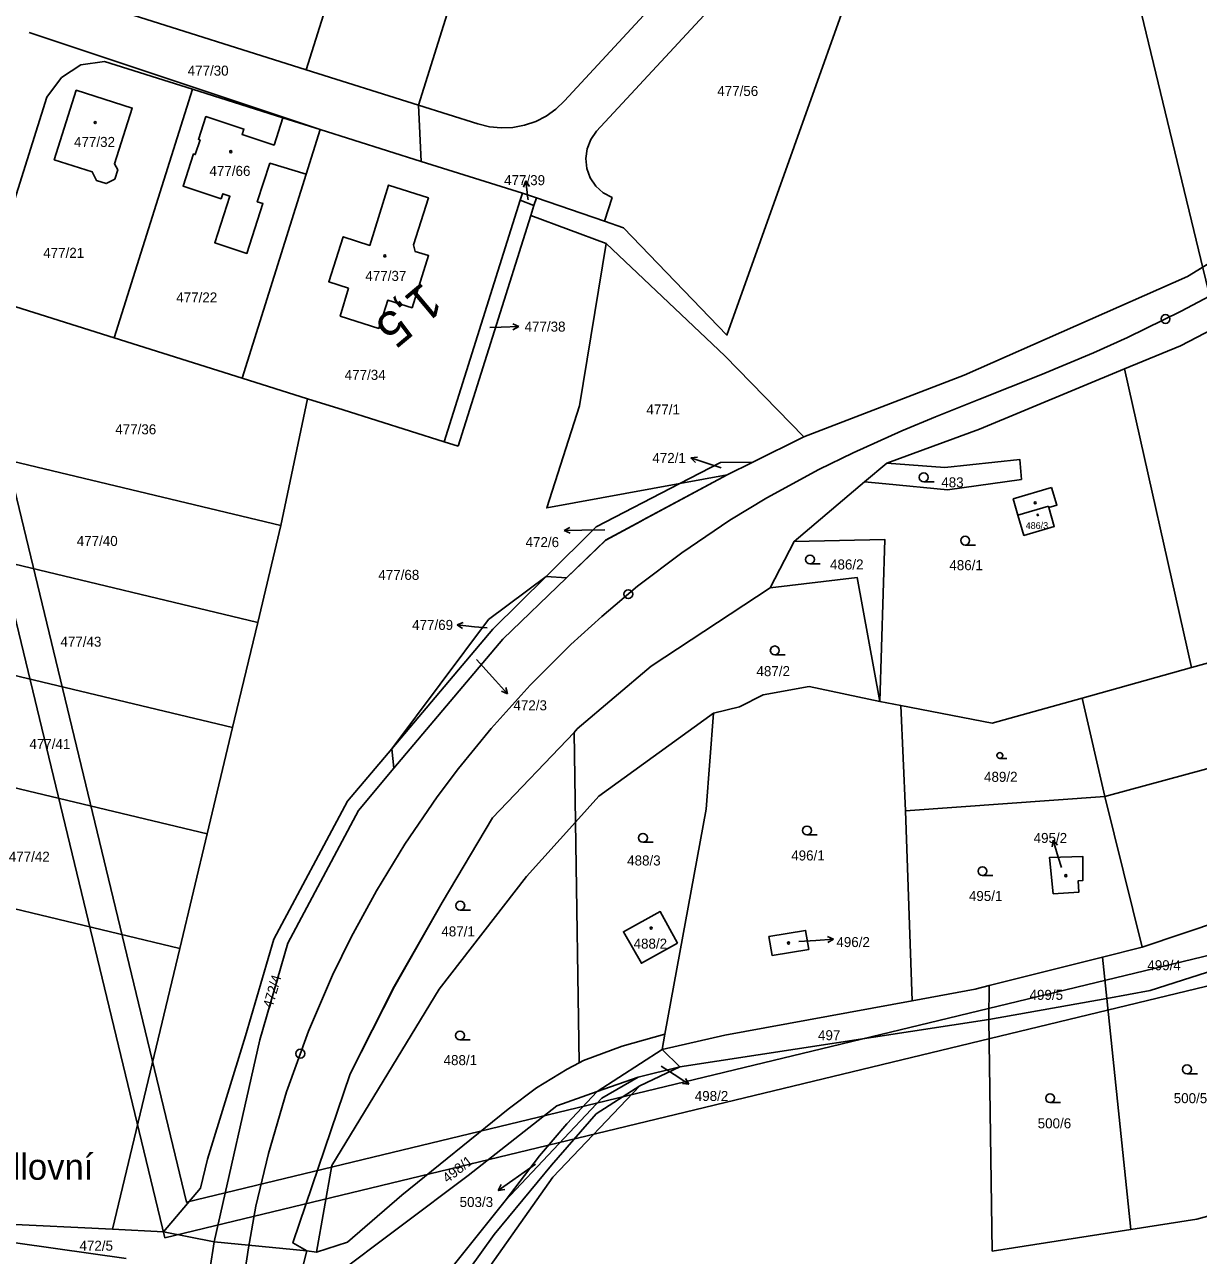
# Model space of a CAD drawing. Extents: x -738085 to -734306, y -1122197 to -1119753.
# Drawn here: x -735509 to -735309.7, y -1120522.6 to -1120313.6 of the extents above; entities that cross this region are included whole.
import ezdxf

# ---------------------------------------------------------------- set-up
doc = ezdxf.new("R2010")
doc.units = 0
for name, color, linetype in [('Hranice parcel', 7, 'Continuous'), ('Parcelní čísla', 7, 'Continuous'), ('Pop  PČ popisy', 7, 'Continuous'), ('SŽDC', 7, 'Continuous'), ('Vnitřní kresba', 7, 'Continuous'), ('Vrstva 1', 7, 'Continuous'), ('Vrstva 53', 7, 'Continuous'), ('Vrstva 7', 7, 'Continuous'), ('Značky budov', 7, 'Continuous'), ('Značky kultur', 7, 'Continuous')]:
    doc.layers.add(name, color=color, linetype=linetype)

msp = doc.modelspace()

# ---------------------------------------------------------------- linework, layer by layer
at = {"layer": 'Hranice parcel'}
for p, q in [((-735355.74, -1120271.01), (-735411.89, -1120331.72)), ((-735442.15, -1120327.29), (-735430.16, -1120289.05)), ((-735461.22, -1120321.27), (-735452.82, -1120294.56)), ((-735461.22, -1120321.27), (-735492.73, -1120311.32)), ((-735508.25, -1120314.94), (-735458.83, -1120331.44)), ((-735495.45, -1120319.9), (-735480.52, -1120324.6)), ((-735442.15, -1120327.29), (-735461.22, -1120321.27)), ((-735493.79, -1120366.81), (-735480.52, -1120324.6)), ((-735480.52, -1120324.6), (-735465.19, -1120329.44)), ((-735441.66, -1120336.85), (-735442.15, -1120327.29)), ((-735465.19, -1120329.44), (-735458.83, -1120331.44)), ((-735458.83, -1120331.44), (-735461.21, -1120339.02)), ((-735458.83, -1120331.44), (-735441.66, -1120336.85)), ((-735441.66, -1120336.85), (-735424.49, -1120342.25)), ((-735472.1, -1120373.63), (-735461.21, -1120339.02)), ((-735424.85, -1120343.41), (-735437.76, -1120384.43)), ((-735424.49, -1120342.25), (-735424.85, -1120343.41)), ((-735422.52, -1120344.32), (-735424.85, -1120343.41)), ((-735422.11, -1120343), (-735424.49, -1120342.25)), ((-735422.52, -1120344.32), (-735422.11, -1120343)), ((-735410.53, -1120347.01), (-735422.11, -1120343)), ((-735423.06, -1120346.03), (-735422.52, -1120344.32)), ((-735435.38, -1120385.18), (-735423.06, -1120346.03)), ((-735423.06, -1120346.03), (-735410.27, -1120350.77)), ((-735515.96, -1120359.84), (-735493.79, -1120366.81)), ((-735493.79, -1120366.81), (-735472.1, -1120373.63)), ((-735312.75, -1120368.12), (-735322.23, -1120372.05)), ((-735322.23, -1120372.05), (-735346.89, -1120382.27)), ((-735322.23, -1120372.05), (-735310.9, -1120422.76)), ((-735472.1, -1120373.63), (-735461, -1120377.12)), ((-735461, -1120377.12), (-735465.48, -1120398.66)), ((-735346.89, -1120382.27), (-735362.63, -1120388.07)), ((-735521.46, -1120385.26), (-735465.48, -1120398.66)), ((-735437.76, -1120384.43), (-735435.38, -1120385.18)), ((-735385.37, -1120387.89), (-735376.69, -1120383.59)), ((-735385.37, -1120387.89), (-735389.72, -1120390.04)), ((-735366.38, -1120391.25), (-735362.63, -1120388.07)), ((-735389.72, -1120390.04), (-735410.38, -1120401.13)), ((-735397.73, -1120391.51), (-735389.72, -1120390.04)), ((-735366.38, -1120391.25), (-735378.33, -1120401.35)), ((-735465.48, -1120398.66), (-735469.43, -1120415.11)), ((-735469.43, -1120415.11), (-735525.43, -1120401.67)), ((-735410.38, -1120401.13), (-735417.02, -1120407.52)), ((-735378.33, -1120401.35), (-735382.4, -1120409.22)), ((-735417.02, -1120407.52), (-735420.46, -1120407.28)), ((-735473.72, -1120432.96), (-735529.4, -1120419.6)), ((-735329.46, -1120427.95), (-735310.9, -1120422.76)), ((-735310.9, -1120422.76), (-735306.34, -1120421.48)), ((-735363.82, -1120428.54), (-735360.21, -1120429.23)), ((-735359.41, -1120447.11), (-735360.21, -1120429.23)), ((-735329.46, -1120427.95), (-735325.59, -1120444.65)), ((-735411.53, -1120444.57), (-735392.02, -1120430.49)), ((-735478, -1120451.01), (-735473.72, -1120432.96)), ((-735415.48, -1120448.98), (-735415.72, -1120433.76)), ((-735533.19, -1120437.76), (-735478, -1120451.01)), ((-735446.67, -1120436.55), (-735446.3, -1120439.84)), ((-735446.3, -1120439.84), (-735452.33, -1120447.02)), ((-735415.48, -1120448.98), (-735411.53, -1120444.57)), ((-735325.59, -1120444.65), (-735359.41, -1120447.11)), ((-735319.23, -1120470.25), (-735325.59, -1120444.65)), ((-735359.41, -1120447.11), (-735358.32, -1120479.32)), ((-735423.77, -1120458.22), (-735415.48, -1120448.98)), ((-735414.84, -1120489.84), (-735415.48, -1120448.98)), ((-735478, -1120451.01), (-735482.68, -1120470.47)), ((-735482.68, -1120470.47), (-735536.55, -1120457.52)), ((-735305.6, -1120465.65), (-735319.23, -1120470.25)), ((-735482.68, -1120470.47), (-735494.09, -1120518.1)), ((-735325.96, -1120471.92), (-735319.23, -1120470.25)), ((-735345.25, -1120476.72), (-735325.96, -1120471.92)), ((-735325.96, -1120471.92), (-735325.23, -1120478.92)), ((-735358.32, -1120479.32), (-735347.6, -1120477.34)), ((-735347.6, -1120477.34), (-735345.25, -1120476.72)), ((-735345.28, -1120482.53), (-735345.25, -1120476.72)), ((-735345.28, -1120482.53), (-735325.23, -1120478.92)), ((-735325.23, -1120478.92), (-735321.15, -1120518.14)), ((-735397.73, -1120490.55), (-735345.28, -1120482.53)), ((-735345.28, -1120482.53), (-735344.7, -1120521.84)), ((-735400.31, -1120485.01), (-735400.75, -1120487.6)), ((-735411.78, -1120494.74), (-735400.75, -1120487.6)), ((-735400.75, -1120487.6), (-735397.73, -1120490.55)), ((-735416.9, -1120490.93), (-735414.84, -1120489.84)), ((-735414.84, -1120489.84), (-735414.13, -1120489.47)), ((-735404.81, -1120492.27), (-735397.73, -1120490.55)), ((-735404.54, -1120493.74), (-735397.73, -1120490.55)), ((-735411.78, -1120494.74), (-735404.81, -1120492.27)), ((-735485.42, -1120518.53), (-735494.09, -1120518.1)), ((-735485.42, -1120518.53), (-735476.81, -1120520.24)), ((-735344.7, -1120521.84), (-735321.15, -1120518.14)), ((-735476.81, -1120520.24), (-735477.58, -1120525)), ((-735476.81, -1120520.24), (-735461.09, -1120521.79)), ((-735462.56, -1120527.51), (-735461.09, -1120521.79)), ((-735461.09, -1120521.79), (-735459.46, -1120522.03))]:
    msp.add_line(p, q, dxfattribs=at)
for points in [[(-735410.53, -1120347.01), (-735407.31, -1120348.13), (-735389.76, -1120366.33), (-735355.74, -1120271.01)], [(-735393.28, -1120300.55), (-735417.35, -1120326.58), (-735418.81, -1120327.96), (-735420.44, -1120329.13), (-735422.23, -1120330.04), (-735424.13, -1120330.7), (-735426.1, -1120331.07), (-735428.1, -1120331.16), (-735430.1, -1120330.96), (-735432.05, -1120330.48), (-735442.15, -1120327.29)], [(-735515.96, -1120359.84), (-735505.22, -1120325.91), (-735502.75, -1120322.57), (-735499.49, -1120320.43), (-735495.45, -1120319.9)], [(-735493.7, -1120339.86), (-735495.14, -1120340.61), (-735496.81, -1120340.08), (-735497.52, -1120338.58), (-735503.98, -1120336.55), (-735500.26, -1120324.77), (-735490.73, -1120327.78), (-735493.76, -1120337.25), (-735493.2, -1120338.24), (-735493.7, -1120339.86)], [(-735232.39, -1120325.34), (-735246.33, -1120333.87), (-735244.86, -1120345.18), (-735245.36, -1120351.86), (-735255.28, -1120352.46), (-735282.27, -1120352.3), (-735312.75, -1120368.12)], [(-735461.21, -1120339.02), (-735467.37, -1120337.15), (-735469.52, -1120343.69), (-735468.56, -1120344.01), (-735471.28, -1120352.47), (-735476.73, -1120350.66), (-735474.14, -1120342.76), (-735475.38, -1120342.32), (-735475.66, -1120343.17), (-735482.1, -1120341.06), (-735480.31, -1120335.58), (-735480.03, -1120335.67), (-735479.22, -1120333.2), (-735479.51, -1120333.11), (-735478.24, -1120329.22), (-735471.78, -1120331.35), (-735472.09, -1120332.29), (-735466.64, -1120334.06), (-735465.19, -1120329.44)], [(-735411.89, -1120331.72), (-735412.88, -1120333.1), (-735413.51, -1120334.68), (-735413.74, -1120336.36), (-735413.55, -1120338.05), (-735412.97, -1120339.64), (-735412.02, -1120341.05), (-735410.76, -1120342.19), (-735409.26, -1120342.99), (-735410.53, -1120347.01)], [(-735286.9, -1120333.84), (-735287.65, -1120341.7), (-735311.53, -1120356.35), (-735349.49, -1120373.13), (-735376.69, -1120383.59)], [(-735454.01, -1120358.35), (-735457.37, -1120357.26), (-735454.9, -1120349.64), (-735450.41, -1120351.09), (-735447.22, -1120340.87), (-735440.45, -1120343.03), (-735442.98, -1120351), (-735442.71, -1120352.13), (-735440.42, -1120352.83), (-735443.22, -1120361.69), (-735447.34, -1120360.4), (-735448.85, -1120365.18), (-735455.41, -1120363.1), (-735454.01, -1120358.35)], [(-735410.27, -1120350.77), (-735414.79, -1120378.32), (-735420.36, -1120395.67), (-735397.73, -1120391.51)], [(-735376.69, -1120383.59), (-735390.09, -1120369.87), (-735410.27, -1120350.77)], [(-735437.76, -1120384.43), (-735454.93, -1120379.03), (-735461, -1120377.12)], [(-735362.63, -1120388.07), (-735352.75, -1120388.8), (-735340.05, -1120387.42), (-735339.74, -1120390.81), (-735352.33, -1120392.58), (-735362.76, -1120391.59), (-735366.38, -1120391.25)], [(-735397.73, -1120391.51), (-735390.83, -1120387.94), (-735385.37, -1120387.89)], [(-735397.73, -1120391.51), (-735411.99, -1120398.89), (-735420.46, -1120407.28)], [(-735334.62, -1120392.17), (-735333.72, -1120395.21), (-735335.07, -1120395.61), (-735334.18, -1120398.81), (-735339.34, -1120400.34), (-735340.35, -1120396.9), (-735341.15, -1120394.14), (-735334.62, -1120392.17)], [(-735378.33, -1120401.35), (-735362.93, -1120401.05), (-735363.82, -1120428.54)], [(-735420.46, -1120407.28), (-735429.53, -1120416.25), (-735446.67, -1120436.55)], [(-735446.67, -1120436.55), (-735430.23, -1120414.58), (-735420.46, -1120407.28)], [(-735417.02, -1120407.52), (-735427.81, -1120417.92), (-735446.3, -1120439.84)], [(-735382.4, -1120409.22), (-735367.65, -1120407.45), (-735363.82, -1120428.54)], [(-735382.4, -1120409.22), (-735402.62, -1120422.52), (-735415.17, -1120433.19), (-735415.72, -1120433.76)], [(-735473.72, -1120432.96), (-735473.38, -1120431.54), (-735469.43, -1120415.11)], [(-735392.02, -1120430.49), (-735387.64, -1120429.44), (-735383.61, -1120427.39), (-735375.77, -1120425.99), (-735363.82, -1120428.54)], [(-735360.21, -1120429.23), (-735344.7, -1120432.21), (-735329.46, -1120427.95)], [(-735400.31, -1120485.01), (-735393.31, -1120446.8), (-735392.02, -1120430.49)], [(-735325.59, -1120444.65), (-735301.59, -1120438.14), (-735287.43, -1120432.85)], [(-735415.72, -1120433.76), (-735429.56, -1120448.26), (-735438.13, -1120462.62), (-735446.2, -1120476.88), (-735453.74, -1120491.74), (-735463.45, -1120520.42), (-735461.09, -1120521.79)], [(-735446.67, -1120436.55), (-735454.18, -1120445.44), (-735466.72, -1120468.88), (-735471.5, -1120485.27), (-735477.98, -1120506.24), (-735479.14, -1120511.16), (-735485.42, -1120518.53)], [(-735452.33, -1120447.02), (-735464.3, -1120469.55), (-735469.07, -1120485.97), (-735476.81, -1120520.24)], [(-735334.35, -1120461.19), (-735334.98, -1120454.98), (-735329.31, -1120454.84), (-735329.33, -1120458.93), (-735330.13, -1120458.99), (-735329.99, -1120460.88), (-735334.35, -1120461.19)], [(-735459.46, -1120522.03), (-735456.84, -1120507.28), (-735438.62, -1120477.35), (-735423.77, -1120458.22)], [(-735398.13, -1120469.53), (-735404.29, -1120472.95), (-735407.34, -1120467.61), (-735401.08, -1120464.19), (-735398.13, -1120469.53)], [(-735375.86, -1120470.63), (-735382.09, -1120471.64), (-735382.63, -1120468.42), (-735376.39, -1120467.38), (-735375.86, -1120470.63)], [(-735325.23, -1120478.92), (-735317.9, -1120477.6), (-735304.09, -1120473.16)], [(-735400.75, -1120487.6), (-735390.11, -1120485.15), (-735358.32, -1120479.32)], [(-735414.13, -1120489.47), (-735407.55, -1120487.04), (-735400.31, -1120485.01)], [(-735459.46, -1120522.03), (-735454.2, -1120520.28), (-735444.98, -1120512.3), (-735426.93, -1120497.72), (-735422.09, -1120494.13), (-735416.9, -1120490.93)], [(-735456.38, -1120569.41), (-735450.21, -1120548.21), (-735429.27, -1120518.99), (-735419.55, -1120507.23), (-735411.94, -1120498.5), (-735404.54, -1120493.74)], [(-735456.38, -1120569.41), (-735447.34, -1120549.4), (-735433.29, -1120529.07), (-735419.31, -1120509.3), (-735404.54, -1120493.74)], [(-735404.81, -1120492.27), (-735411, -1120495.85), (-735427.41, -1120513.29)], [(-735462.56, -1120527.51), (-735456.92, -1120526.44), (-735433.71, -1120508.99), (-735418.63, -1120497.17), (-735411.78, -1120494.74)], [(-735427.41, -1120513.29), (-735421.61, -1120505.63), (-735416.95, -1120500.24), (-735411.78, -1120494.74)], [(-735494.09, -1120518.1), (-735512.93, -1120517.17), (-735538.99, -1120511.95), (-735547.27, -1120507.12)], [(-735549.79, -1120512.96), (-735543.29, -1120514.47), (-735516.24, -1120519.64), (-735491.79, -1120523.07)], [(-735427.41, -1120513.29), (-735447.57, -1120538.45), (-735453.3, -1120549.98)], [(-735321.15, -1120518.14), (-735309.98, -1120516.38), (-735306.01, -1120515.3)]]:
    msp.add_lwpolyline(points, dxfattribs=at)
at = {"layer": 'Pop  PČ popisy'}
for p, q in [((-735423.92, -1120340.14), (-735424.29, -1120341.2)), ((-735423.55, -1120343.12), (-735423.92, -1120340.14)), ((-735423.92, -1120340.14), (-735423.3, -1120341.07)), ((-735423.52, -1120343.34), (-735423.55, -1120343.12)), ((-735425.12, -1120364.88), (-735426.14, -1120364.41)), ((-735430.03, -1120365.04), (-735428.12, -1120364.98)), ((-735428.12, -1120364.98), (-735425.12, -1120364.88)), ((-735425.12, -1120364.88), (-735426.1, -1120365.41)), ((-735395.87, -1120387.18), (-735394.77, -1120387.02)), ((-735393.02, -1120388.11), (-735395.87, -1120387.18)), ((-735395.87, -1120387.18), (-735395.08, -1120387.97)), ((-735390.74, -1120388.85), (-735393.02, -1120388.11)), ((-735417.4, -1120399.48), (-735416.41, -1120398.96)), ((-735414.4, -1120399.43), (-735417.4, -1120399.48)), ((-735417.4, -1120399.48), (-735416.39, -1120399.97)), ((-735410.48, -1120399.36), (-735414.4, -1120399.43)), ((-735435.59, -1120415.51), (-735434.55, -1120415.11)), ((-735432.61, -1120415.82), (-735435.59, -1120415.51)), ((-735435.59, -1120415.51), (-735434.65, -1120416.11)), ((-735430.47, -1120416.03), (-735432.61, -1120415.82)), ((-735432.26, -1120421.42), (-735429.03, -1120424.97)), ((-735429.03, -1120424.97), (-735427.02, -1120427.2)), ((-735427.02, -1120427.2), (-735428.06, -1120426.79)), ((-735427.02, -1120427.2), (-735427.32, -1120426.12)), ((-735334.38, -1120452.09), (-735334.56, -1120453.19)), ((-735333.5, -1120454.96), (-735334.38, -1120452.09)), ((-735334.38, -1120452.09), (-735333.61, -1120452.9)), ((-735332.97, -1120456.69), (-735333.5, -1120454.96)), ((-735377.53, -1120469.25), (-735374.64, -1120469.07)), ((-735374.64, -1120469.07), (-735371.65, -1120468.86)), ((-735371.65, -1120468.86), (-735372.68, -1120468.43)), ((-735371.65, -1120468.86), (-735372.61, -1120469.43)), ((-735400.9, -1120490.43), (-735398.73, -1120491.86)), ((-735398.73, -1120491.86), (-735396.21, -1120493.49)), ((-735396.21, -1120493.49), (-735397.33, -1120493.37)), ((-735396.21, -1120493.49), (-735396.78, -1120492.53)), ((-735422.26, -1120507.08), (-735426.14, -1120509.79)), ((-735426.14, -1120509.79), (-735428.6, -1120511.51)), ((-735428.6, -1120511.51), (-735428.07, -1120510.53)), ((-735428.6, -1120511.51), (-735427.49, -1120511.35))]:
    msp.add_line(p, q, dxfattribs=at)
at = {"layer": 'SŽDC'}
for p, q in [((-735322.23, -1120372.05), (-735312.75, -1120368.12)), ((-735346.89, -1120382.27), (-735322.23, -1120372.05)), ((-735362.63, -1120388.07), (-735346.89, -1120382.27)), ((-735376.69, -1120383.59), (-735385.37, -1120387.89)), ((-735385.37, -1120387.89), (-735389.72, -1120390.04)), ((-735366.38, -1120391.25), (-735362.63, -1120388.07)), ((-735389.72, -1120390.04), (-735410.38, -1120401.13)), ((-735378.33, -1120401.35), (-735366.38, -1120391.25)), ((-735410.38, -1120401.13), (-735417.02, -1120407.52)), ((-735382.4, -1120409.22), (-735378.33, -1120401.35)), ((-735446.3, -1120439.84), (-735452.33, -1120447.02)), ((-735476.81, -1120520.24), (-735461.09, -1120521.79))]:
    msp.add_line(p, q, dxfattribs=at)
for points in [[(-735312.75, -1120368.12), (-735282.27, -1120352.3), (-735255.28, -1120352.46), (-735245.36, -1120351.86), (-735244.86, -1120345.18), (-735246.33, -1120333.87), (-735232.39, -1120325.34)], [(-735286.9, -1120333.84), (-735287.65, -1120341.7), (-735311.53, -1120356.35), (-735349.49, -1120373.13), (-735376.69, -1120383.59)], [(-735417.02, -1120407.52), (-735427.81, -1120417.92), (-735446.3, -1120439.84)], [(-735415.72, -1120433.76), (-735415.17, -1120433.19), (-735402.62, -1120422.52), (-735382.4, -1120409.22)], [(-735461.09, -1120521.79), (-735463.45, -1120520.42), (-735453.74, -1120491.74), (-735446.2, -1120476.88), (-735438.13, -1120462.62), (-735429.56, -1120448.26), (-735415.72, -1120433.76)], [(-735452.33, -1120447.02), (-735464.3, -1120469.55), (-735469.07, -1120485.97), (-735476.81, -1120520.24)]]:
    msp.add_lwpolyline(points, dxfattribs=at)
at = {"layer": 'Vnitřní kresba'}
for p, q in [((-735335.14, -1120395.37), (-735340.35, -1120396.9)), ((-735335.07, -1120395.61), (-735335.14, -1120395.37))]:
    msp.add_line(p, q, dxfattribs=at)
at = {"layer": 'Vrstva 1'}
for points in [[(-734534.27, -1119984.39), (-735554.91, -1120230.88), (-735485.2, -1120519.57), (-734464.55, -1120273.08)], [(-734470.58, -1120269.4), (-735481.51, -1120513.53), (-735548.88, -1120234.56), (-734537.95, -1119990.43)], [(-734541.63, -1119996.45), (-735348.44, -1120191.3), (-735283.42, -1120460.56), (-734476.61, -1120265.71)]]:
    msp.add_lwpolyline(points, close=True, dxfattribs=at)
msp.add_lwpolyline([(-735304.06, -1120357.75), (-735312.6, -1120362.28), (-735321.76, -1120366.74), (-735327.51, -1120369.32), (-735336.44, -1120373.09), (-735346.98, -1120377.26), (-735354.33, -1120380.21), (-735360.07, -1120382.6), (-735368.33, -1120386.31), (-735374.16, -1120389.16), (-735382.98, -1120393.95), (-735389.27, -1120397.76), (-735397.43, -1120403.28), (-735404.93, -1120408.97), (-735411.01, -1120414.07), (-735416.27, -1120418.85), (-735423.16, -1120425.73), (-735429.79, -1120433.1), (-735435.35, -1120439.92), (-735438.96, -1120444.69), (-735444.43, -1120452.73), (-735449.27, -1120460.68), (-735453.57, -1120468.51), (-735456.72, -1120474.99), (-735460.8, -1120484.48), (-735464.55, -1120494.8), (-735467.61, -1120505.27), (-735469.73, -1120514.19), (-735471.02, -1120521.28), (-735472.03, -1120528.02)], dxfattribs=at)
at = {"layer": 'Vrstva 53'}
for points in [[(-735476.81, -1120520.24), (-735469.07, -1120485.97), (-735464.3, -1120469.55), (-735452.33, -1120447.02), (-735446.3, -1120439.84), (-735427.81, -1120417.92), (-735417.02, -1120407.52), (-735410.34, -1120401.13), (-735404.44, -1120397.94), (-735404, -1120397.71), (-735389.72, -1120390.04), (-735385.37, -1120387.89), (-735376.69, -1120383.59), (-735349.49, -1120373.13), (-735311.53, -1120356.35), (-735287.63, -1120341.7), (-735286.9, -1120333.84), (-735286.41, -1120325.76), (-735288.06, -1120321.06), (-735267.54, -1120311.77), (-735247.23, -1120302.41)], [(-735232.39, -1120325.34), (-735246.33, -1120333.87), (-735244.86, -1120345.18), (-735245.38, -1120351.86), (-735255.28, -1120352.46), (-735282.27, -1120352.3), (-735312.75, -1120368.12), (-735322.23, -1120372.05), (-735346.89, -1120382.27), (-735362.63, -1120388.07), (-735366.38, -1120391.25), (-735378.33, -1120401.35), (-735382.4, -1120409.22), (-735402.62, -1120422.52), (-735415.17, -1120433.19), (-735415.72, -1120433.76), (-735429.56, -1120448.26), (-735438.13, -1120462.62), (-735446.24, -1120476.88), (-735453.74, -1120491.74), (-735463.45, -1120520.42), (-735461.09, -1120521.79), (-735476.81, -1120520.24)]]:
    msp.add_lwpolyline(points, dxfattribs=at)
at = {"layer": 'Vrstva 7'}
for centre in [(-735315.29, -1120363.59), (-735406.51, -1120410.3), (-735462.19, -1120488.3)]:
    msp.add_circle(centre, 0.75, dxfattribs=at)
at = {"layer": 'Značky budov'}
for centre, radius in [((-735497.02, -1120330.25), 0.175), ((-735474.02, -1120335.18), 0.175), ((-735447.85, -1120352.89), 0.175), ((-735337.41, -1120394.81), 0.175), ((-735336.97, -1120396.85), 0.117), ((-735332.22, -1120458.09), 0.175), ((-735402.64, -1120466.98), 0.175), ((-735379.29, -1120469.52), 0.175)]:
    msp.add_circle(centre, radius, dxfattribs=at)
at = {"layer": 'Značky kultur'}
for p, q in [((-735356.34, -1120391.22), (-735354.59, -1120391.22)), ((-735349.31, -1120401.96), (-735347.56, -1120401.96)), ((-735375.65, -1120405.17), (-735373.9, -1120405.17)), ((-735381.64, -1120420.6), (-735379.89, -1120420.6)), ((-735343.42, -1120438.2), (-735342.24, -1120438.2)), ((-735404.02, -1120452.43), (-735402.27, -1120452.43)), ((-735376.17, -1120451.16), (-735374.42, -1120451.16)), ((-735346.37, -1120458.08), (-735344.62, -1120458.08)), ((-735435.04, -1120463.93), (-735433.29, -1120463.93)), ((-735435.09, -1120485.97), (-735433.34, -1120485.97)), ((-735311.63, -1120491.72), (-735309.88, -1120491.72)), ((-735334.88, -1120496.62), (-735333.13, -1120496.62))]:
    msp.add_line(p, q, dxfattribs=at)
for centre, radius in [((-735356.34, -1120390.47), 0.75), ((-735349.31, -1120401.21), 0.75), ((-735375.65, -1120404.42), 0.75), ((-735381.64, -1120419.85), 0.75), ((-735343.42, -1120437.7), 0.502), ((-735376.17, -1120450.41), 0.75), ((-735404.02, -1120451.68), 0.75), ((-735346.37, -1120457.33), 0.75), ((-735435.04, -1120463.18), 0.75), ((-735435.09, -1120485.22), 0.75), ((-735311.63, -1120490.97), 0.75), ((-735334.88, -1120495.87), 0.75)]:
    msp.add_circle(centre, radius, dxfattribs=at)

# ---------------------------------------------------------------- texts
at = {"layer": 'Parcelní čísla'}
for s, height, p in [('477/30', 1.7, (-735481.33, -1120322.28)), ('477/56', 1.7, (-735391.4, -1120325.74)), ('477/32', 1.7, (-735500.62, -1120334.38)), ('477/66', 1.7, (-735477.62, -1120339.3)), ('477/39', 1.7, (-735427.59, -1120340.87)), ('477/21', 1.7, (-735505.85, -1120353.21)), ('477/37', 1.7, (-735451.15, -1120357.12)), ('477/22', 1.7, (-735483.26, -1120360.78)), ('477/38', 1.7, (-735424.12, -1120365.73)), ('477/34', 1.7, (-735454.66, -1120373.92)), ('477/1', 1.7, (-735403.43, -1120379.8)), ('477/36', 1.7, (-735493.62, -1120383.17)), ('472/1', 1.7, (-735402.42, -1120388.03)), ('483', 1.7, (-735353.36, -1120392.17)), ('486/3', 1.14, (-735339.03, -1120399.22)), ('477/40', 1.7, (-735500.16, -1120402.12)), ('472/6', 1.7, (-735423.95, -1120402.32)), ('486/2', 1.7, (-735372.25, -1120406.11)), ('477/68', 1.7, (-735448.95, -1120407.88)), ('486/1', 1.7, (-735351.99, -1120406.23)), ('477/69', 1.7, (-735443.21, -1120416.37)), ('477/43', 1.7, (-735502.93, -1120419.22)), ('487/2', 1.7, (-735384.74, -1120424.22)), ('472/3', 1.7, (-735426.01, -1120430.02)), ('477/41', 1.7, (-735508.2, -1120436.59)), ('489/2', 1.7, (-735346.1, -1120442.16)), ('495/2', 1.7, (-735337.68, -1120452.54)), ('477/42', 1.7, (-735511.7, -1120455.72)), ('496/1', 1.7, (-735378.84, -1120455.51)), ('488/3', 1.7, (-735406.7, -1120456.36)), ('495/1', 1.7, (-735348.67, -1120462.39)), ('487/1', 1.7, (-735438.25, -1120468.4)), ('488/2', 1.7, (-735405.61, -1120470.48)), ('496/2', 1.7, (-735371.17, -1120470.21)), ('499/4', 1.7, (-735318.37, -1120474.14)), ('499/5', 1.7, (-735338.37, -1120479.17)), ('497', 1.7, (-735374.29, -1120486.02)), ('488/1', 1.7, (-735437.87, -1120490.25)), ('498/2', 1.7, (-735395.22, -1120496.34)), ('500/5', 1.7, (-735313.89, -1120496.71)), ('500/6', 1.7, (-735336.99, -1120500.98)), ('503/3', 1.7, (-735435.15, -1120514.34)), ('472/5', 1.7, (-735499.7, -1120521.76))]:
    msp.add_text(s, height=height, dxfattribs=at).set_placement(p)
for s, rotation, p in [('472/4', 74, (-735466.95, -1120480.7)), ('498/1', 38, (-735437.22, -1120510.35))]:
    msp.add_text(s, height=1.7, rotation=rotation, dxfattribs=at).set_placement(p)
at = {"layer": 'Pop  PČ popisy'}
msp.add_text('Handlovní', height=4.4, dxfattribs=at).set_placement((-735523.83, -1120509.71))
at = {"layer": 'Vrstva 7'}
msp.add_text('1,5', height=6, rotation=219.9701, dxfattribs=at).set_placement((-735441.35, -1120357.12))

doc.saveas('drawing.dxf')
